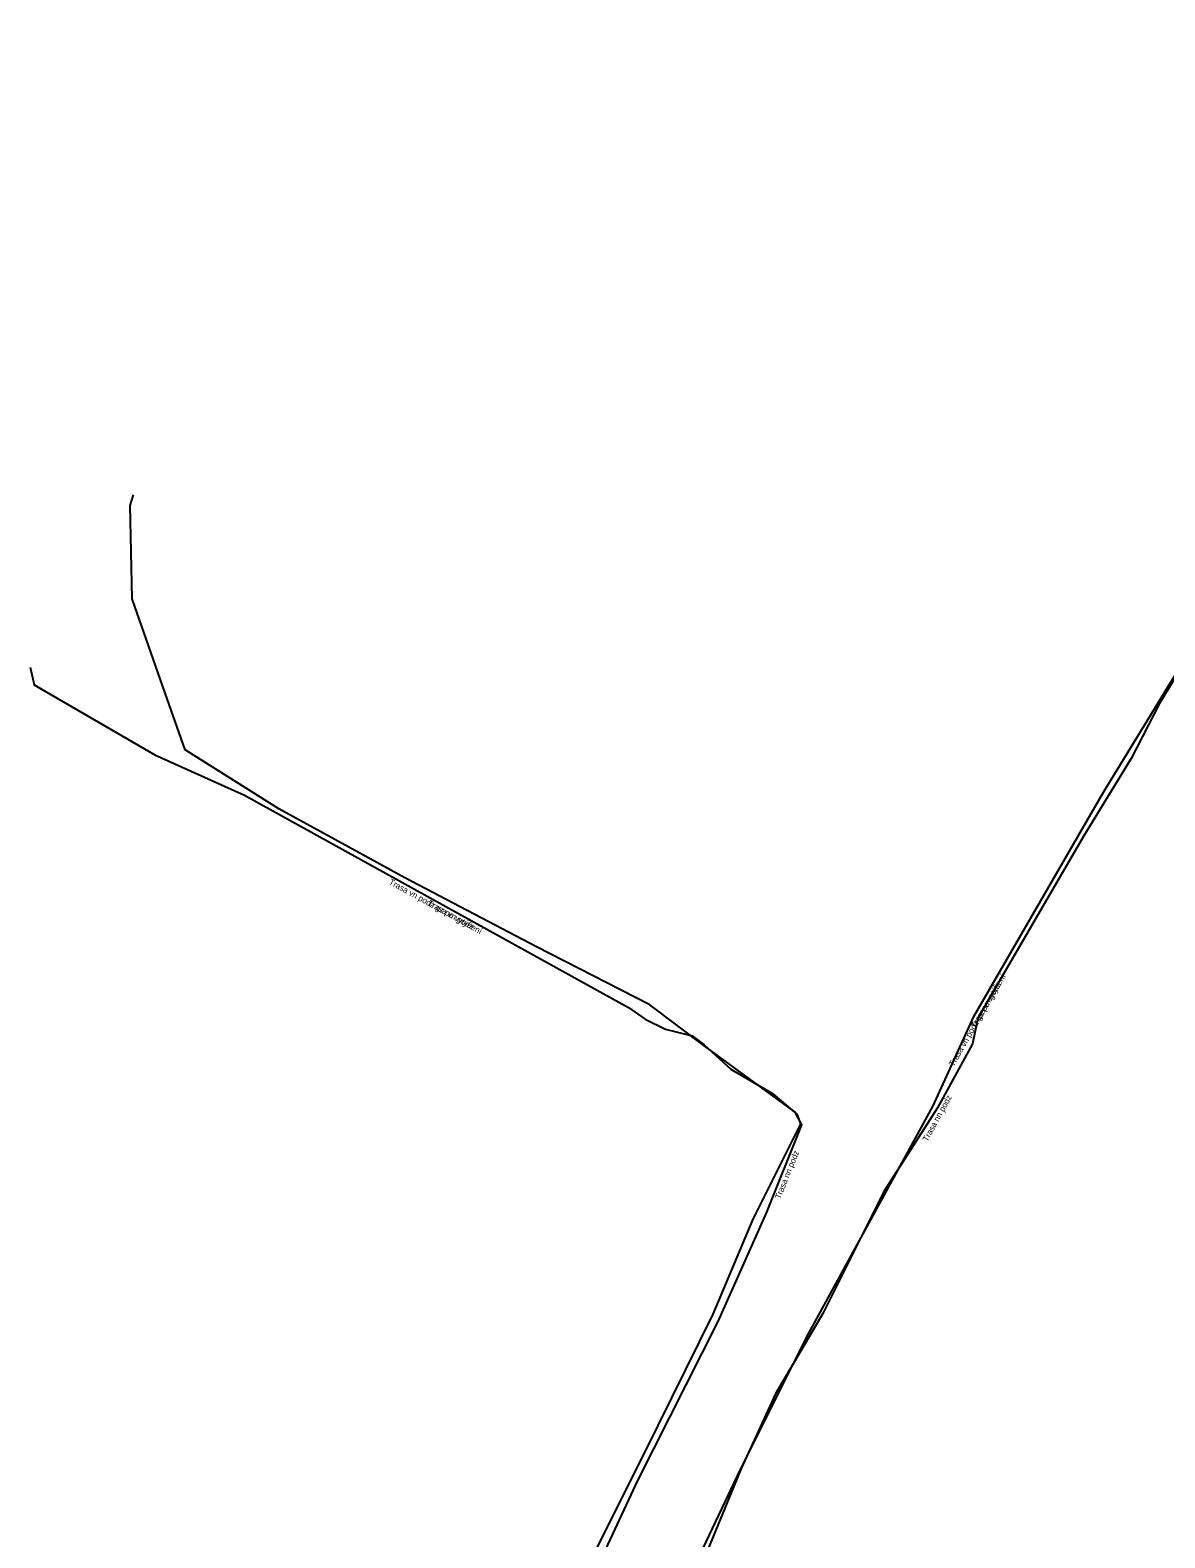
# Model space of a CAD drawing. Extents: x -528089 to -527692, y -1079306 to -1078676.
# Drawn here: x -527995.6 to -527901, y -1078858 to -1078732.4 of the extents above; entities that cross this region are included whole.
import ezdxf

# ---------------------------------------------------------------- set-up
doc = ezdxf.new("R2010")
doc.units = 0
for name, color, linetype in [('Popiskový text - Ostatní atributy Trasy', 7, 'Continuous'), ('Spojnice NN', 7, 'Continuous'), ('Spojnice VN', 7, 'Continuous')]:
    doc.layers.add(name, color=color, linetype=linetype)

msp = doc.modelspace()

# ---------------------------------------------------------------- linework, layer by layer
at = {"layer": 'Spojnice NN'}
for points in [[(-527876.15, -1078748.62), (-527881.08, -1078755.7), (-527890.34, -1078770.34), (-527895.52, -1078778.72), (-527901.44, -1078788.43), (-527903.84, -1078793.06), (-527907.78, -1078799.52), (-527916.61, -1078814.71), (-527917.06, -1078816.84), (-527919.98, -1078822.17), (-527924.47, -1078829.21), (-527929.52, -1078839.3), (-527933.49, -1078846.02), (-527936.34, -1078852.24), (-527940.87, -1078863.22), (-527944.75, -1078870.23), (-527946.26, -1078873.7), (-527951.36, -1078883.98), (-527955.3, -1078891.37), (-527954.1, -1078893.05), (-527952.62, -1078893.82), (-527950.35, -1078896.83)], [(-527950.35, -1078896.83), (-527952.69, -1078894.24), (-527954.78, -1078893.15), (-527955.55, -1078894.04), (-527962.13, -1078891.61), (-527962.23, -1078891.53), (-527962.29, -1078888.88), (-527956.54, -1078877.05), (-527952.15, -1078868.66), (-527944.96, -1078853.24), (-527938.27, -1078839.97), (-527934.2, -1078830.87), (-527931.28, -1078823.59), (-527931.84, -1078822.54), (-527939.45, -1078816.99), (-527943.96, -1078813.58), (-527953.39, -1078808.77), (-527964.38, -1078803), (-527974.88, -1078797.26), (-527982.7, -1078792.34), (-527984.36, -1078787.62), (-527987.11, -1078779.76), (-527987.28, -1078772), (-527986.99, -1078771.09)]]:
    msp.add_lwpolyline(points, dxfattribs=at)
at = {"layer": 'Spojnice VN'}
for points in [[(-527950.35, -1078896.83), (-527953.4, -1078892.8), (-527953.13, -1078886.8), (-527946.25, -1078873.1), (-527936.41, -1078852.32), (-527930.88, -1078841.27), (-527920.34, -1078822.02), (-527916.96, -1078814.57), (-527906.15, -1078795.86), (-527889.87, -1078769.33), (-527884.73, -1078761.54), (-527875.38, -1078747), (-527869.33, -1078736.87), (-527867.99, -1078733.54), (-527866.55, -1078732.38)], [(-527950.35, -1078896.83), (-527953.4, -1078892.8), (-527953.13, -1078886.8), (-527946.25, -1078873.1), (-527936.41, -1078852.32), (-527930.88, -1078841.27), (-527920.34, -1078822.02), (-527916.96, -1078814.57), (-527906.15, -1078795.86), (-527889.87, -1078769.33), (-527884.73, -1078761.54), (-527875.38, -1078747), (-527869.33, -1078736.87), (-527867.99, -1078733.54), (-527866.55, -1078732.38)], [(-527995.61, -1078785.45), (-527995.27, -1078786.93), (-527985.21, -1078792.77), (-527977.73, -1078796.13), (-527945.74, -1078813.81), (-527944.35, -1078814.78), (-527942.66, -1078815.63), (-527940.42, -1078816.19), (-527939.43, -1078816.92), (-527937.2, -1078818.96), (-527933.73, -1078820.99), (-527931.69, -1078822.69), (-527931.4, -1078823.52), (-527935.37, -1078831.45)], [(-527995.61, -1078785.45), (-527995.27, -1078786.93), (-527985.21, -1078792.77), (-527977.73, -1078796.13), (-527945.74, -1078813.81), (-527944.35, -1078814.78), (-527942.66, -1078815.63), (-527940.42, -1078816.19), (-527939.43, -1078816.92), (-527937.2, -1078818.96), (-527933.73, -1078820.99), (-527931.69, -1078822.69), (-527931.4, -1078823.52), (-527935.37, -1078831.45)], [(-527935.37, -1078831.45), (-527938.69, -1078839.37), (-527943.3, -1078848.64), (-527948.68, -1078859.44), (-527960.15, -1078882.56), (-527962.22, -1078887.48), (-527962.47, -1078887.86), (-527956.55, -1078890.83), (-527953.82, -1078893.17), (-527950.35, -1078896.83)], [(-527935.37, -1078831.45), (-527938.69, -1078839.37), (-527943.3, -1078848.64), (-527948.68, -1078859.44), (-527960.15, -1078882.56), (-527962.22, -1078887.48), (-527962.47, -1078887.86), (-527956.55, -1078890.83), (-527953.82, -1078893.17), (-527950.35, -1078896.83)]]:
    msp.add_lwpolyline(points, dxfattribs=at)

# ---------------------------------------------------------------- texts
at = {"layer": 'Popiskový text - Ostatní atributy Trasy'}
for s, rotation, p in [('Trasa vn podz gz po vytýèení', 331.0718, (-527965.75, -1078803.5)), ('Trasa vn podz', 331.0718, (-527962.52, -1078805.28)), ('Trasa vn podz gz po vytýèení', 59.9821, (-527918.63, -1078818.77)), ('Trasa vn podz', 59.9821, (-527916.79, -1078815.57)), ('Trasa nn podz', 61.2842, (-527920.81, -1078825.03)), ('Trasa nn podz', 68.1443, (-527933.08, -1078829.82))]:
    msp.add_text(s, height=0.5, rotation=rotation, dxfattribs=at).set_placement(p)

doc.saveas('drawing.dxf')
